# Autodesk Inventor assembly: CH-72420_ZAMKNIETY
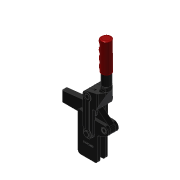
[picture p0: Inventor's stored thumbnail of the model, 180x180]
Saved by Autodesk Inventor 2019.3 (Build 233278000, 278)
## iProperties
Company: Î¢ÈíÖÐ¹ú
Created: 2013-06
Part Number: CH-72420_ZAMKNIETY
Material: Ogólny
Description: STEP AP203
Document SubType Name: Assembly
Designer: CADENGINEERING4
Stock Number: DOCISK CIĘŻKI
Sending System: SolidWorks 2011
Preprocessor: SwSTEP 2.0
Title: CH-72420.STEP
Author: Î¢ÈíÓÃ»§
Revision Number: ÈÎºÎ
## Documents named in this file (12)
- D:\Vault_2016\Projekty\NASZ KATALOG\CLAMPTEK\STRONA\Heavy duty weldables\CH-72420\CH-72420_ZAMKNIETY.iam
- D:\Vault_2016\Projekty\NASZ KATALOG\CLAMPTEK\STRONA\Heavy duty weldables\CH-72420\72425-08.ipt
- D:\Vault_2016\Projekty\NASZ KATALOG\CLAMPTEK\STRONA\Heavy duty weldables\CH-72420\72425-03.ipt
- D:\Vault_2016\Projekty\NASZ KATALOG\CLAMPTEK\STRONA\Heavy duty weldables\CH-72420\72425-06.ipt
- D:\Vault_2016\Projekty\NASZ KATALOG\CLAMPTEK\STRONA\Heavy duty weldables\CH-72420\CH-72420-02.ipt
- D:\Vault_2016\Projekty\NASZ KATALOG\CLAMPTEK\STRONA\Heavy duty weldables\CH-72420\72425-07.ipt
- D:\Vault_2016\Projekty\NASZ KATALOG\CLAMPTEK\STRONA\Heavy duty weldables\CH-72420\72425-10.ipt
- D:\Vault_2016\Projekty\NASZ KATALOG\CLAMPTEK\STRONA\Heavy duty weldables\CH-72420\M12.ipt
- D:\Vault_2016\Projekty\NASZ KATALOG\CLAMPTEK\STRONA\Heavy duty weldables\CH-72420\72415-04.ipt
- D:\Vault_2016\Projekty\NASZ KATALOG\CLAMPTEK\STRONA\Heavy duty weldables\CH-72420\72425-11.ipt
- D:\Vault_2016\Projekty\NASZ KATALOG\CLAMPTEK\STRONA\Heavy duty weldables\CH-72420\CH-72420-01.ipt
- D:\Vault_2016\Projekty\NASZ KATALOG\CLAMPTEK\STRONA\Heavy duty weldables\CH-72420\72425-09.ipt
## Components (18 placed, 18 different names)
1. 72425-08_1
2. 72425-03_2
3. 72425-08_3
4. 72425-06_4
5. 72425-03_5
6. 72425-06_6
7. CH-72420-02_7 — Kątowe:2
8. 72425-07_8
9. 72425-10_9
10. 72425-06_10
11. M12_11
12. 72425-06_12
13. 72425-06_13
14. 72415-04_14
15. 72425-11_15
16. 72425-06_16
17. CH-72420-01_17 — Kątowe:2
18. 72425-09_18
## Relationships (1: Angle 1)
- Kątowe:2 [Angle]: CH-72420-02_7 ↔ CH-72420-01_17
